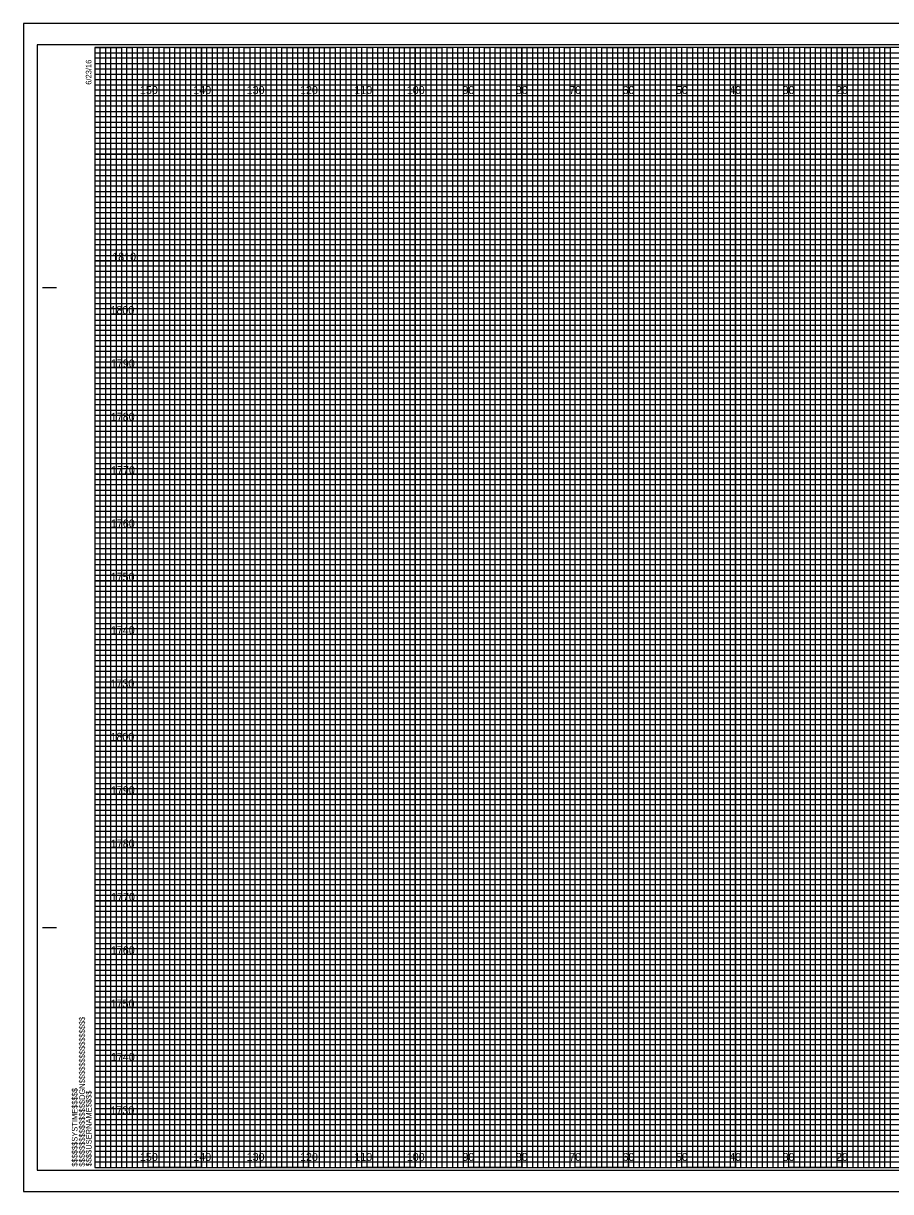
# Model space of a CAD drawing. Extents: x -15 to 323, y -5 to 6170.
# Drawn here: x -13.4 to 149.1, y 1315.5 to 1534.5 of the extents above; entities that cross this region are included whole.
import ezdxf

# ---------------------------------------------------------------- set-up
doc = ezdxf.new("R2010")
doc.units = 0
for name, color, linetype in [('Prop XS DDE', 7, 'Continuous'), ('Prop XS DDE Slope Text', 7, 'Continuous'), ('Prop XS DDE Text', 7, 'Continuous'), ('Prop XS Earthwork Shape', 7, 'Continuous'), ('Prop XS Noise Wall', 7, 'Continuous'), ('Prop XS Retaining Wall', 7, 'Continuous'), ('Prop XS Station Labels', 7, 'Continuous'), ('Scratch_Level_3', 7, 'Continuous'), ('Scratch_Level_7', 7, 'Continuous'), ('Scratch_Level_8', 7, 'Continuous'), ('Sheet Cross Section Grid Minor 1 CELL', 7, 'Continuous')]:
    doc.layers.add(name, color=color, linetype=linetype)

msp = doc.modelspace()

# ---------------------------------------------------------------- linework, layer by layer
at = {"layer": 'Prop XS DDE'}
msp.add_lwpolyline([(-13.4, 1315.5), (323.3, 1315.5), (323.3, 1534.5), (-13.4, 1534.5)], close=True, dxfattribs=at)
at = {"layer": 'Prop XS DDE Slope Text'}
msp.add_lwpolyline([(-10.8, 1319.5), (322.4, 1319.5), (322.4, 1530.5), (-10.8, 1530.5)], close=True, dxfattribs=at)
at = {"layer": 'Prop XS DDE Text'}
for p, q in [((10, 1320), (10, 1530)), ((20, 1320), (20, 1530)), ((30, 1320), (30, 1530)), ((40, 1320), (40, 1530)), ((50, 1320), (50, 1530)), ((60, 1320), (60, 1530)), ((70, 1320), (70, 1530)), ((80, 1320), (80, 1530)), ((90, 1320), (90, 1530)), ((100, 1320), (100, 1530)), ((110, 1320), (110, 1530)), ((120, 1320), (120, 1530)), ((130, 1320), (130, 1530)), ((140, 1320), (140, 1530)), ((0, 1520), (320, 1520)), ((0, 1510), (320, 1510)), ((0, 1500), (320, 1500)), ((0, 1490), (320, 1490)), ((0, 1480), (320, 1480)), ((0, 1470), (320, 1470)), ((0, 1460), (320, 1460)), ((0, 1450), (320, 1450)), ((0, 1440), (320, 1440)), ((0, 1430), (320, 1430)), ((0, 1420), (320, 1420)), ((0, 1410), (320, 1410)), ((0, 1400), (320, 1400)), ((0, 1390), (320, 1390)), ((0, 1380), (320, 1380)), ((0, 1370), (320, 1370)), ((0, 1360), (320, 1360)), ((0, 1350), (320, 1350)), ((0, 1340), (320, 1340)), ((0, 1330), (320, 1330))]:
    msp.add_line(p, q, dxfattribs=at)
at = {"layer": 'Prop XS Earthwork Shape'}
for p, q in [((10, 1530), (0, 1530)), ((10, 1320), (10, 1530)), ((30, 1530), (20, 1530)), ((20, 1530), (20, 1320)), ((30, 1320), (30, 1530)), ((50, 1530), (40, 1530)), ((40, 1530), (40, 1320)), ((50, 1320), (50, 1530)), ((70, 1530), (60, 1530)), ((60, 1530), (60, 1320)), ((70, 1320), (70, 1530)), ((90, 1530), (80, 1530)), ((80, 1530), (80, 1320)), ((90, 1320), (90, 1530)), ((110, 1530), (100, 1530)), ((100, 1530), (100, 1320)), ((110, 1320), (110, 1530)), ((130, 1530), (120, 1530)), ((120, 1530), (120, 1320)), ((130, 1320), (130, 1530)), ((150, 1530), (140, 1530)), ((140, 1530), (140, 1320)), ((20, 1320), (10, 1320)), ((40, 1320), (30, 1320)), ((60, 1320), (50, 1320)), ((80, 1320), (70, 1320)), ((100, 1320), (90, 1320)), ((120, 1320), (110, 1320)), ((140, 1320), (130, 1320))]:
    msp.add_line(p, q, dxfattribs=at)
for points in [[(0, 1520), (320, 1520), (320, 1510), (0, 1510)], [(0, 1500), (320, 1500), (320, 1490), (0, 1490)], [(0, 1480), (320, 1480), (320, 1470), (0, 1470)], [(0, 1460), (320, 1460), (320, 1450), (0, 1450)], [(0, 1440), (320, 1440), (320, 1430), (0, 1430)], [(0, 1420), (320, 1420), (320, 1410), (0, 1410)], [(0, 1400), (320, 1400), (320, 1390), (0, 1390)], [(0, 1380), (320, 1380), (320, 1370), (0, 1370)], [(0, 1360), (320, 1360), (320, 1350), (0, 1350)], [(0, 1340), (320, 1340), (320, 1330), (0, 1330)]]:
    msp.add_lwpolyline(points, dxfattribs=at)
at = {"layer": 'Prop XS Noise Wall'}
for p, q in [((-9.8, 1485), (-7.3, 1485)), ((-9.7, 1485), (-7.2, 1485)), ((-9.8, 1365), (-7.3, 1365)), ((-9.7, 1365), (-7.2, 1365)), ((0, 1320), (0, 1320)), ((0, 1320), (0, 1320)), ((0, 1320), (0, 1320)), ((0, 1320), (0, 1320)), ((0, 1320), (0, 1320)), ((0, 1320), (0, 1320)), ((0, 1320), (0, 1320))]:
    msp.add_line(p, q, dxfattribs=at)
msp.add_lwpolyline([(320, 1530), (0, 1530), (0, 1320), (320, 1320)], close=True, dxfattribs=at)
at = {"layer": 'Prop XS Retaining Wall'}
for points in [[(0, 1320), (1, 1320), (1, 1530), (2, 1530), (2, 1320)], [(2, 1320), (3, 1320), (3, 1530), (4, 1530), (4, 1320)], [(5, 1320), (6, 1320), (6, 1530), (7, 1530), (7, 1320)], [(7, 1320), (8, 1320), (8, 1530), (9, 1530), (9, 1320)], [(10, 1320), (11, 1320), (11, 1530), (12, 1530), (12, 1320)], [(12, 1320), (13, 1320), (13, 1530), (14, 1530), (14, 1320)], [(15, 1320), (16, 1320), (16, 1530), (17, 1530), (17, 1320)], [(17, 1320), (18, 1320), (18, 1530), (19, 1530), (19, 1320)], [(20, 1320), (21, 1320), (21, 1530), (22, 1530), (22, 1320)], [(22, 1320), (23, 1320), (23, 1530), (24, 1530), (24, 1320)], [(25, 1320), (26, 1320), (26, 1530), (27, 1530), (27, 1320)], [(27, 1320), (28, 1320), (28, 1530), (29, 1530), (29, 1320)], [(30, 1320), (31, 1320), (31, 1530), (32, 1530), (32, 1320)], [(32, 1320), (33, 1320), (33, 1530), (34, 1530), (34, 1320)], [(35, 1320), (36, 1320), (36, 1530), (37, 1530), (37, 1320)], [(37, 1320), (38, 1320), (38, 1530), (39, 1530), (39, 1320)], [(40, 1320), (41, 1320), (41, 1530), (42, 1530), (42, 1320)], [(42, 1320), (43, 1320), (43, 1530), (44, 1530), (44, 1320)], [(45, 1320), (46, 1320), (46, 1530), (47, 1530), (47, 1320)], [(47, 1320), (48, 1320), (48, 1530), (49, 1530), (49, 1320)], [(50, 1320), (51, 1320), (51, 1530), (52, 1530), (52, 1320)], [(52, 1320), (53, 1320), (53, 1530), (54, 1530), (54, 1320)], [(55, 1320), (56, 1320), (56, 1530), (57, 1530), (57, 1320)], [(57, 1320), (58, 1320), (58, 1530), (59, 1530), (59, 1320)], [(60, 1320), (61, 1320), (61, 1530), (62, 1530), (62, 1320)], [(62, 1320), (63, 1320), (63, 1530), (64, 1530), (64, 1320)], [(65, 1320), (66, 1320), (66, 1530), (67, 1530), (67, 1320)], [(67, 1320), (68, 1320), (68, 1530), (69, 1530), (69, 1320)], [(70, 1320), (71, 1320), (71, 1530), (72, 1530), (72, 1320)], [(72, 1320), (73, 1320), (73, 1530), (74, 1530), (74, 1320)], [(75, 1320), (76, 1320), (76, 1530), (77, 1530), (77, 1320)], [(77, 1320), (78, 1320), (78, 1530), (79, 1530), (79, 1320)], [(80, 1320), (81, 1320), (81, 1530), (82, 1530), (82, 1320)], [(82, 1320), (83, 1320), (83, 1530), (84, 1530), (84, 1320)], [(85, 1320), (86, 1320), (86, 1530), (87, 1530), (87, 1320)], [(87, 1320), (88, 1320), (88, 1530), (89, 1530), (89, 1320)], [(90, 1320), (91, 1320), (91, 1530), (92, 1530), (92, 1320)], [(92, 1320), (93, 1320), (93, 1530), (94, 1530), (94, 1320)], [(95, 1320), (96, 1320), (96, 1530), (97, 1530), (97, 1320)], [(97, 1320), (98, 1320), (98, 1530), (99, 1530), (99, 1320)], [(100, 1320), (101, 1320), (101, 1530), (102, 1530), (102, 1320)], [(102, 1320), (103, 1320), (103, 1530), (104, 1530), (104, 1320)], [(105, 1320), (106, 1320), (106, 1530), (107, 1530), (107, 1320)], [(107, 1320), (108, 1320), (108, 1530), (109, 1530), (109, 1320)], [(110, 1320), (111, 1320), (111, 1530), (112, 1530), (112, 1320)], [(112, 1320), (113, 1320), (113, 1530), (114, 1530), (114, 1320)], [(115, 1320), (116, 1320), (116, 1530), (117, 1530), (117, 1320)], [(117, 1320), (118, 1320), (118, 1530), (119, 1530), (119, 1320)], [(120, 1320), (121, 1320), (121, 1530), (122, 1530), (122, 1320)], [(122, 1320), (123, 1320), (123, 1530), (124, 1530), (124, 1320)], [(125, 1320), (126, 1320), (126, 1530), (127, 1530), (127, 1320)], [(127, 1320), (128, 1320), (128, 1530), (129, 1530), (129, 1320)], [(130, 1320), (131, 1320), (131, 1530), (132, 1530), (132, 1320)], [(132, 1320), (133, 1320), (133, 1530), (134, 1530), (134, 1320)], [(135, 1320), (136, 1320), (136, 1530), (137, 1530), (137, 1320)], [(137, 1320), (138, 1320), (138, 1530), (139, 1530), (139, 1320)], [(140, 1320), (141, 1320), (141, 1530), (142, 1530), (142, 1320)], [(142, 1320), (143, 1320), (143, 1530), (144, 1530), (144, 1320)], [(145, 1320), (146, 1320), (146, 1530), (147, 1530), (147, 1320)], [(147, 1320), (148, 1320), (148, 1530), (149, 1530), (149, 1320)]]:
    msp.add_lwpolyline(points, dxfattribs=at)
at = {"layer": 'Prop XS Station Labels'}
for points in [[(0, 1530), (5, 1530), (5, 1320), (15, 1320), (15, 1530), (25, 1530), (25, 1320), (35, 1320), (35, 1530), (45, 1530), (45, 1320), (55, 1320), (55, 1530), (65, 1530), (65, 1320), (75, 1320), (75, 1530), (85, 1530), (85, 1320), (95, 1320), (95, 1530), (105, 1530), (105, 1320), (115, 1320), (115, 1530), (125, 1530), (125, 1320), (135, 1320), (135, 1530), (145, 1530), (145, 1320), (155, 1320)], [(0, 1525), (275, 1525)], [(0, 1505), (320, 1505), (320, 1515), (0, 1515)], [(0, 1485), (320, 1485), (320, 1495), (0, 1495)], [(0, 1465), (320, 1465), (320, 1475), (0, 1475)], [(0, 1445), (320, 1445), (320, 1455), (0, 1455)], [(0, 1425), (320, 1425), (320, 1435), (0, 1435)], [(0, 1405), (320, 1405), (320, 1415), (0, 1415)], [(0, 1385), (320, 1385), (320, 1395), (0, 1395)], [(0, 1365), (320, 1365), (320, 1375), (0, 1375)], [(0, 1345), (320, 1345), (320, 1355), (0, 1355)], [(0, 1325), (320, 1325), (320, 1335), (0, 1335)]]:
    msp.add_lwpolyline(points, dxfattribs=at)
at = {"layer": 'Scratch_Level_7'}
for p, q in [((323.3, 1534.5), (-13.4, 1534.5)), ((-13.4, 1534.5), (-13.4, 1315.5)), ((-13.4, 1315.5), (323.3, 1315.5))]:
    msp.add_line(p, q, dxfattribs=at)
at = {"layer": 'Sheet Cross Section Grid Minor 1 CELL'}
for p, q in [((0, 1529), (260, 1529)), ((260, 1527.98), (0, 1527.98)), ((0, 1527.98), (0, 1527)), ((0, 1527), (260, 1527)), ((260, 1525.89), (0, 1525.89)), ((0, 1525.89), (0, 1524)), ((0, 1524), (320, 1524))]:
    msp.add_line(p, q, dxfattribs=at)
for points in [[(0, 1523), (270, 1523), (320, 1523), (320, 1522), (0, 1522)], [(0, 1521), (320, 1521), (320, 1519), (0, 1519)], [(0, 1518), (320, 1518), (320, 1517), (0, 1516.98)], [(0, 1516), (320, 1516), (320, 1514), (0, 1514)], [(0, 1513), (320, 1513), (320, 1512), (0, 1512)], [(0, 1511), (320, 1511), (320, 1509), (0, 1509)], [(0, 1508), (320, 1508), (320, 1507), (0, 1507)], [(0, 1506), (320, 1506), (320, 1504), (0, 1504)], [(0, 1503), (320, 1503), (320, 1502), (0, 1502)], [(0, 1501), (320, 1501), (320, 1499), (0, 1499)], [(0, 1498), (320, 1498), (320, 1497), (0, 1497)], [(0, 1496), (320, 1496), (320, 1493.95), (320, 1493), (320, 1492), (0, 1492)], [(0, 1494), (320, 1494), (320, 1493), (0, 1493)], [(0, 1491), (320, 1491), (320, 1489), (0, 1489.03)], [(0, 1489.03), (320, 1489), (320, 1488), (0, 1488)], [(0, 1487), (320, 1487), (320, 1486), (0, 1486)], [(0, 1484), (320, 1484), (320, 1483), (0, 1483)], [(0, 1482), (320, 1482), (320, 1481), (0, 1481)], [(-0.07, 1478.89), (320, 1478.89), (320, 1477.88), (-0.07, 1477.88)], [(0, 1477), (320, 1477), (320, 1476), (0, 1476)], [(0, 1474), (320, 1474), (320, 1473), (0, 1473)], [(0, 1472), (320, 1472), (320, 1471), (0, 1471)], [(0, 1469), (320, 1469), (320, 1468), (0, 1468)], [(0, 1467), (320, 1467), (320, 1466), (0, 1466)], [(0, 1464), (320, 1464), (320, 1463), (0, 1463)], [(0, 1462), (320, 1462), (320, 1461), (0, 1461)], [(0, 1459), (320, 1459), (319.99, 1457.98), (0, 1458)], [(0, 1457), (320, 1457), (320, 1456), (0, 1456)], [(0, 1454), (320, 1454), (320, 1453), (0, 1453)], [(0, 1452), (320, 1452), (320, 1451), (0, 1451)], [(0, 1449), (320, 1449), (320, 1448), (0, 1448)], [(0, 1447), (320, 1447), (320, 1446), (0, 1446)], [(0, 1444), (320, 1444), (320, 1443), (0, 1443)], [(0, 1442), (320, 1442), (320, 1441), (0, 1441)], [(0, 1439), (320, 1439), (320, 1438), (0, 1438)], [(0, 1436.99), (320.07, 1436.91), (320, 1436), (0, 1436)], [(0, 1434), (320, 1434), (320, 1433), (0, 1433)], [(0, 1432), (320, 1432), (320, 1431), (0, 1431)], [(0, 1429), (320, 1429), (320, 1428), (0, 1428)], [(0, 1427), (320, 1427), (320, 1426), (0, 1426)], [(0, 1424), (320, 1424), (320, 1423), (0, 1423)], [(0, 1422), (320, 1422), (320, 1421), (0, 1421)], [(0, 1419), (320, 1419), (320, 1418), (0, 1418)], [(0, 1417), (320, 1417), (320, 1416), (0, 1416)], [(0, 1414), (320, 1414), (320, 1413), (0, 1413)], [(0, 1412), (320, 1412), (320, 1411), (0, 1411)], [(0, 1409), (320, 1409), (320, 1408), (0, 1408)], [(0, 1407), (320, 1407), (320, 1406), (0, 1406)], [(0, 1404), (320, 1404), (320, 1403), (0, 1403)], [(0, 1402), (320, 1402), (320, 1401), (0, 1401)], [(0, 1399), (320, 1399), (319.99, 1397.98), (0, 1398)], [(0, 1397), (320, 1397), (320, 1396), (0, 1396)], [(0, 1394), (320, 1394), (320, 1393), (0, 1393)], [(0, 1392), (320, 1392), (320, 1391), (0, 1391)], [(0, 1389), (320, 1389), (320, 1388), (0, 1388)], [(0, 1387), (320, 1387), (320, 1386), (0, 1386)], [(0, 1384), (320, 1384), (320, 1383), (0, 1383)], [(0, 1382), (320, 1382), (320, 1381), (0, 1381)], [(0, 1379), (320, 1379), (320, 1378), (0, 1378)], [(0, 1376.99), (320.07, 1376.91), (320, 1376), (0, 1376)], [(0, 1374), (320, 1374), (320, 1373), (0, 1373)], [(0, 1372), (320, 1372), (320, 1371), (0, 1371)], [(0, 1369), (320, 1369), (320, 1368), (0, 1368)], [(0, 1367), (320, 1367), (320, 1366), (0, 1366)], [(0, 1364), (320, 1364), (320, 1363), (0, 1363)], [(0, 1362), (320, 1362), (320, 1361), (0, 1361)], [(0, 1359), (320, 1359), (320, 1358), (0, 1358)], [(0, 1357), (320, 1357), (320, 1356), (0, 1356)], [(0, 1354), (320, 1354), (320, 1353), (0, 1353)], [(0, 1352), (320, 1352), (320, 1351), (0, 1351)], [(0, 1349), (320, 1349), (320, 1348), (0, 1348)], [(0, 1347), (320, 1347), (320, 1346), (0, 1346)], [(0, 1344), (320, 1344), (320, 1343), (0, 1343)], [(0, 1342), (320, 1342), (320, 1341), (0, 1341)], [(0, 1339), (320, 1339), (320, 1338), (0, 1338)], [(0, 1337), (320, 1337), (320, 1336), (0, 1336)], [(0, 1334), (320, 1334), (320, 1333), (0, 1333)], [(0, 1332), (320, 1332), (320, 1331), (0, 1331)], [(0, 1329), (320, 1329), (320, 1328), (0, 1328)], [(0, 1327), (320, 1327), (320, 1326), (0, 1326)], [(0, 1324), (320, 1324), (320, 1323), (0, 1323)], [(0, 1322), (320, 1322), (320, 1321), (0, 1321)]]:
    msp.add_lwpolyline(points, dxfattribs=at)

# ---------------------------------------------------------------- texts
at = {"layer": 'Prop XS Noise Wall'}
for s, p in [('6/23/16', (-0.65, 1523)), ('$$$$$$$$$$$$$$$$DGN$$$$$$$$$$$$$$$$', (-1.88, 1320.18)), ('$$$$$$SYSTIME$$$$$', (-3.26, 1320.18)), ('$$$$USERNAME$$$$', (-0.62, 1320.23))]:
    msp.add_text(s, height=1.05, rotation=90, dxfattribs=at).set_placement(p)
at = {"layer": 'Scratch_Level_3'}
for s, p in [('1810', (3.25, 1490)), ('1800', (2.92, 1480)), ('1790', (3, 1470)), ('1780', (2.98, 1460)), ('1770', (3.04, 1450)), ('1760', (3, 1440)), ('1750', (2.96, 1430)), ('1740', (3, 1420)), ('1730', (2.92, 1410)), ('1800', (2.92, 1400)), ('1790', (3, 1390)), ('1780', (2.98, 1380)), ('1770', (3.04, 1370)), ('1760', (3, 1360)), ('1750', (2.96, 1350)), ('1740', (3, 1340)), ('1730', (2.92, 1330))]:
    msp.add_text(s, height=1.5, dxfattribs=at).set_placement(p)
at = {"layer": 'Scratch_Level_8'}
for s, p in [('150', (8.44, 1521.25)), ('140', (18.44, 1521.25)), ('130', (28.44, 1521.25)), ('120', (38.44, 1521.25)), ('110', (48.62, 1521.25)), ('100', (58.44, 1521.25)), ('90', (68.86, 1521.25)), ('80', (78.86, 1521.25)), ('70', (88.86, 1521.25)), ('60', (98.86, 1521.25)), ('50', (108.86, 1521.25)), ('40', (118.86, 1521.25)), ('30', (128.86, 1521.25)), ('20', (138.86, 1521.25)), ('150', (8.44, 1321.25)), ('140', (18.44, 1321.25)), ('130', (28.44, 1321.25)), ('120', (38.44, 1321.25)), ('110', (48.62, 1321.25)), ('100', (58.44, 1321.25)), ('90', (68.86, 1321.25)), ('80', (78.86, 1321.25)), ('70', (88.86, 1321.25)), ('60', (98.86, 1321.25)), ('50', (108.86, 1321.25)), ('40', (118.86, 1321.25)), ('30', (128.86, 1321.25)), ('20', (138.86, 1321.25))]:
    msp.add_text(s, height=1.5, dxfattribs=at).set_placement(p)

doc.saveas('drawing.dxf')
